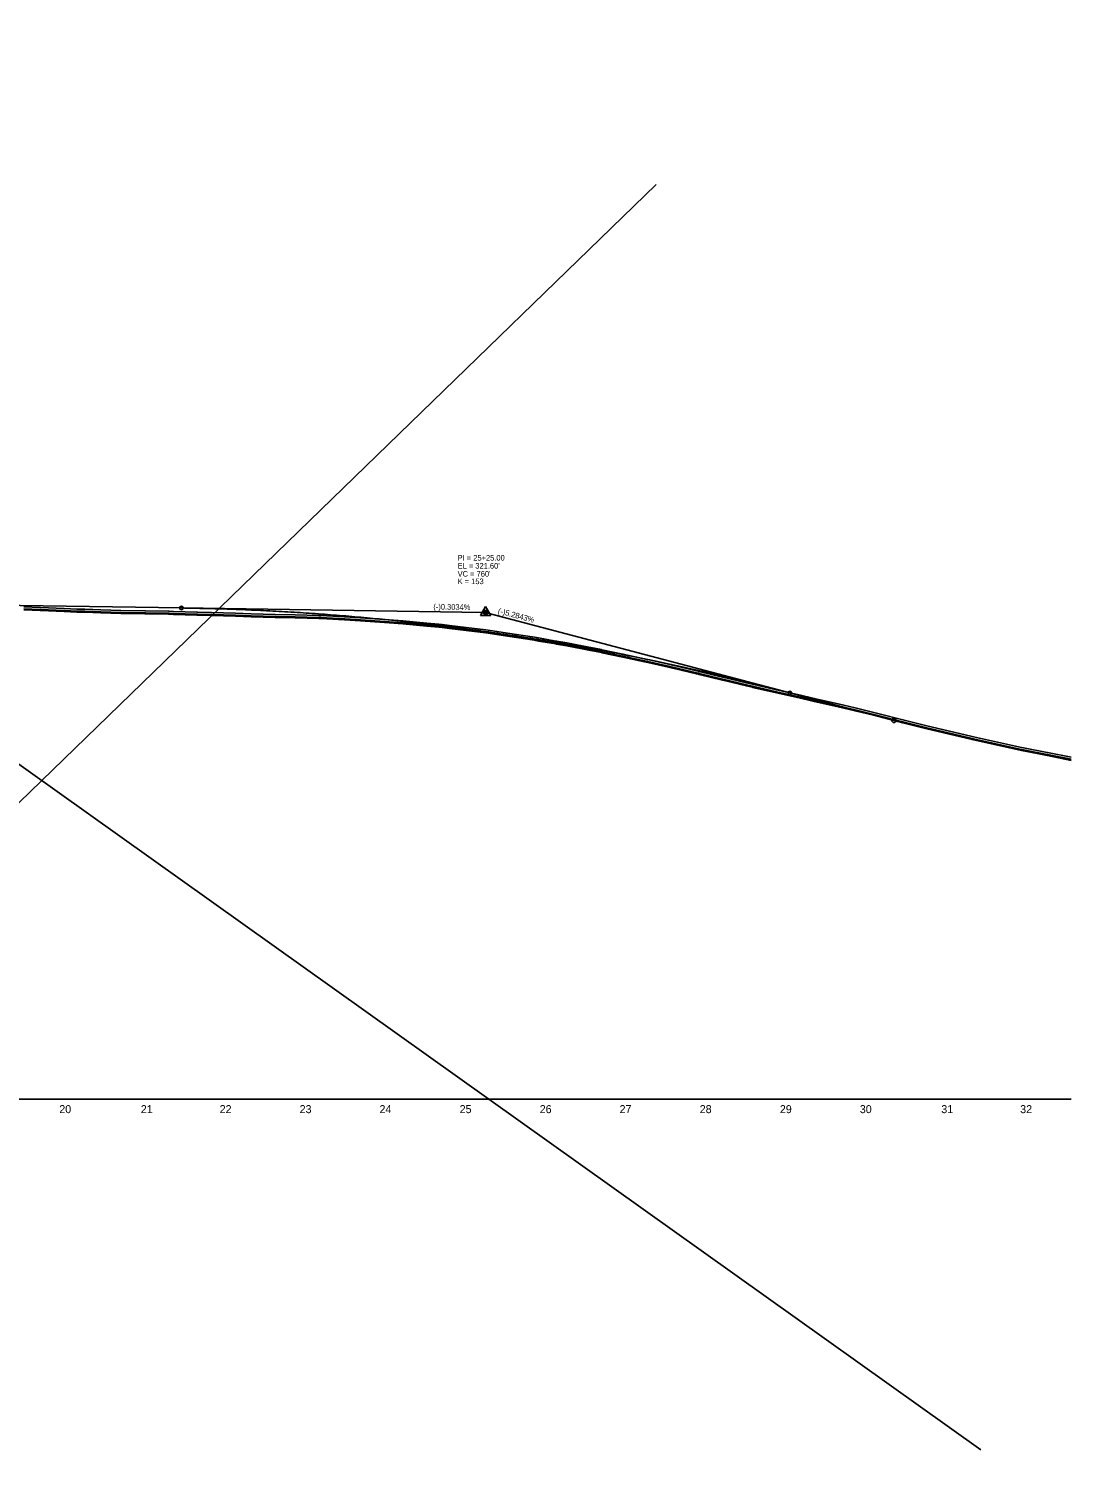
# Model space of a CAD drawing. Extents: x 2111382 to 2119088, y 667477 to 672158.
# Drawn here: x 2117786 to 2119088, y 670365 to 672158 of the extents above; entities that cross this region are included whole.
import ezdxf

# ---------------------------------------------------------------- set-up
doc = ezdxf.new("R2010")
doc.units = 0
for name, color, linetype in [('Exist Profile Cell', 7, 'Continuous'), ('Exist Vertical Profile Ground Line', 7, 'Continuous'), ('Exist Vertical Profile Horizontal Axis Label Major', 7, 'Continuous'), ('Prop PFL VPI Symbol CELL', 7, 'Continuous'), ('Prop Vertical Profile Curve Label', 7, 'Continuous'), ('Prop Vertical Profile Grade', 7, 'Continuous'), ('Prop Vertical Profile Grade Label', 7, 'Continuous'), ('Prop VPI Label', 7, 'Continuous'), ('Scratch_Level_2', 7, 'Continuous'), ('Scratch_Level_3', 7, 'Continuous')]:
    doc.layers.add(name, color=color, linetype=linetype)

msp = doc.modelspace()

# ---------------------------------------------------------------- linework, layer by layer
at = {"layer": 'Exist Profile Cell'}
msp.add_line((2116831.9, 670820.2), (2119088.5, 670820.2), dxfattribs=at)
at = {"layer": 'Exist Vertical Profile Ground Line'}
for points in [[(2117779.9, 671431.7), (2117800.2, 671431), (2117800.7, 671430.9), (2117830.4, 671429.6), (2117846, 671428.9), (2117856.2, 671428.6), (2117876, 671428), (2117876.3, 671428), (2117901.3, 671427.2), (2117931.3, 671426.7), (2117931.8, 671426.7), (2117960.5, 671426.1), (2117961.4, 671426.1), (2117966.8, 671426), (2117996.2, 671425.1), (2117996.8, 671425.1), (2118014.1, 671424.6), (2118014.5, 671424.6), (2118044.4, 671423.6), (2118063.8, 671423), (2118093.8, 671422.2), (2118119, 671421.6), (2118148.6, 671420.8), (2118149.1, 671420.8), (2118150.7, 671420.7), (2118151.2, 671420.7), (2118180.7, 671419.1), (2118181, 671419.1), (2118200.5, 671418), (2118230.6, 671415.8), (2118253.6, 671414.2), (2118283.5, 671411.4), (2118298.6, 671410), (2118302.5, 671409.7), (2118311.9, 671408.5), (2118332.5, 671406), (2118357, 671403), (2118387.2, 671398.4), (2118415.1, 671394.1), (2118415.5, 671394), (2118423, 671392.7), (2118444.6, 671389), (2118445.5, 671388.8), (2118458.5, 671386.5), (2118487.8, 671380.9), (2118488.4, 671380.8), (2118501.6, 671378.2), (2118502.2, 671378.1), (2118528.4, 671372.6), (2118555.2, 671366.7), (2118555.6, 671366.6), (2118585.3, 671360.1), (2118590.2, 671358.9), (2118590.8, 671358.7), (2118620.2, 671351.7), (2118622.8, 671351.1), (2118623.5, 671350.9), (2118652.8, 671343.8), (2118653.3, 671343.7), (2118682.7, 671336.5), (2118690, 671334.9), (2118690.3, 671334.8), (2118720.2, 671328), (2118750, 671321.1), (2118763.8, 671318), (2118767.4, 671317.2), (2118797.3, 671310.4), (2118818.4, 671305.3), (2118848.5, 671298.2)], [(2118848.5, 671298.2), (2118878.2, 671290.6), (2118908.1, 671283.1), (2118934.5, 671276.7), (2118964.5, 671269.5), (2118966.5, 671269.1), (2118996.4, 671262.5), (2119026.4, 671255.9), (2119028.6, 671255.4), (2119058.5, 671249.5), (2119058.9, 671249.5), (2119088.5, 671243.6)]]:
    msp.add_lwpolyline(points, dxfattribs=at)
at = {"layer": 'Prop PFL VPI Symbol CELL'}
for p, q in [((2118356.9, 671435.7), (2118350.4, 671424.5)), ((2118356.9, 671435.7), (2118363.4, 671424.5)), ((2118350.4, 671424.5), (2118363.4, 671424.5))]:
    msp.add_line(p, q, dxfattribs=at)
for radius in [1.75, 1.2]:
    msp.add_circle((2118356.9, 671428.2), radius, dxfattribs=at)
at = {"layer": 'Prop Vertical Profile Curve Label'}
for centre in [(2117976.9, 671434), (2118736.9, 671327.8)]:
    msp.add_circle(centre, 2.25, dxfattribs=at)
at = {"layer": 'Prop Vertical Profile Grade'}
for p, q in [((2117706.9, 671438.1), (2117976.9, 671434)), ((2118736.9, 671327.8), (2118866.9, 671293.5))]:
    msp.add_line(p, q, dxfattribs=at)
msp.add_spline([(2117976.9, 671434), (2117992.1, 671433.7), (2118007.3, 671433.4), (2118022.5, 671433), (2118037.7, 671432.5), (2118052.9, 671431.9), (2118068.1, 671431.3), (2118083.3, 671430.5), (2118098.5, 671429.7), (2118113.7, 671428.9), (2118128.9, 671427.9), (2118144.1, 671426.9), (2118159.3, 671425.8), (2118174.5, 671424.6), (2118189.7, 671423.4), (2118204.9, 671422), (2118220.1, 671420.6), (2118235.3, 671419.1), (2118250.5, 671417.6), (2118265.7, 671416), (2118280.9, 671414.2), (2118296.1, 671412.5), (2118311.3, 671410.6), (2118326.5, 671408.7), (2118341.7, 671406.7), (2118356.9, 671404.6), (2118372.1, 671402.4), (2118387.3, 671400.2), (2118402.5, 671397.9), (2118417.7, 671395.5), (2118432.9, 671393), (2118448.1, 671390.5), (2118463.3, 671387.9), (2118478.5, 671385.2), (2118493.7, 671382.4), (2118508.9, 671379.6), (2118524.1, 671376.6), (2118539.3, 671373.6), (2118554.5, 671370.6), (2118569.7, 671367.4), (2118584.9, 671364.2), (2118600.1, 671360.9), (2118615.3, 671357.5), (2118630.5, 671354.1), (2118645.7, 671350.6), (2118660.9, 671347), (2118676.1, 671343.3), (2118691.3, 671339.5), (2118706.5, 671335.7), (2118721.7, 671331.8), (2118736.9, 671327.8)], degree=3, dxfattribs=at)
at = {"layer": 'Prop VPI Label'}
for p, q in [((2117976.9, 671434), (2118354.1, 671428.3)), ((2118736.9, 671327.8), (2118359.5, 671427.5))]:
    msp.add_line(p, q, dxfattribs=at)
for centre in [(2118356.9, 671428.2), (2118866.9, 671293.5)]:
    msp.add_circle(centre, 2.75, dxfattribs=at)
at = {"layer": 'Scratch_Level_2'}
for points in [[(2117779.9, 671433), (2117800.2, 671432.2), (2117800.7, 671432.2), (2117830.4, 671430.9), (2117846, 671430.2), (2117856.2, 671429.9), (2117876, 671429.3), (2117876.3, 671429.3), (2117901.3, 671428.5), (2117931.3, 671427.9), (2117931.8, 671427.9), (2117960.5, 671427.4), (2117961.4, 671427.4), (2117966.8, 671427.2), (2117996.2, 671426.4), (2117996.8, 671426.3), (2118014.1, 671425.8), (2118014.5, 671425.8), (2118044.4, 671424.9), (2118063.8, 671424.2), (2118093.8, 671423.5), (2118119, 671422.9), (2118148.6, 671422), (2118149.1, 671422), (2118150.7, 671422), (2118151.2, 671421.9), (2118180.7, 671420.3), (2118181, 671420.3), (2118200.5, 671419.3), (2118230.6, 671417.1), (2118253.6, 671415.4), (2118283.5, 671412.7), (2118298.6, 671411.3), (2118302.5, 671410.9), (2118311.9, 671409.8), (2118332.5, 671407.3), (2118357, 671404.3), (2118387.2, 671399.6), (2118415.1, 671395.3), (2118415.5, 671395.3), (2118423, 671394), (2118444.6, 671390.2), (2118445.5, 671390.1), (2118458.5, 671387.8), (2118487.8, 671382.1), (2118488.4, 671382), (2118501.6, 671379.5), (2118502.2, 671379.3), (2118528.4, 671373.8), (2118555.2, 671367.9), (2118555.6, 671367.8), (2118585.3, 671361.3), (2118590.2, 671360.1), (2118590.8, 671360), (2118620.2, 671353), (2118622.8, 671352.4), (2118623.5, 671352.2), (2118652.8, 671345.1), (2118653.3, 671344.9), (2118682.7, 671337.8), (2118690, 671336.1), (2118690.3, 671336.1), (2118720.2, 671329.2), (2118750, 671322.4), (2118763.8, 671319.3), (2118767.4, 671318.5), (2118797.3, 671311.6), (2118818.4, 671306.6), (2118848.5, 671299.4)], [(2118848.5, 671299.4), (2118878.2, 671291.9), (2118908.1, 671284.3), (2118934.5, 671278), (2118964.5, 671270.8), (2118966.5, 671270.3), (2118996.4, 671263.7), (2119026.4, 671257.1), (2119028.6, 671256.7), (2119058.5, 671250.8), (2119058.9, 671250.7), (2119088.5, 671244.9)]]:
    msp.add_lwpolyline(points, dxfattribs=at)
at = {"layer": 'Scratch_Level_3'}
for p, q in [((2116483.7, 672157.9), (2118975.5, 670382)), ((2116922.9, 670365.1), (2118570, 671963.4))]:
    msp.add_line(p, q, dxfattribs=at)
for points in [[(2117779.9, 671435.5), (2117800.2, 671434.7), (2117800.7, 671434.7), (2117830.4, 671433.4), (2117846, 671432.7), (2117856.2, 671432.4), (2117876, 671431.8), (2117876.3, 671431.8), (2117901.3, 671431), (2117931.3, 671430.4), (2117931.8, 671430.4), (2117960.5, 671429.9), (2117961.4, 671429.9), (2117966.8, 671429.7), (2117996.2, 671428.9), (2117996.8, 671428.8), (2118014.1, 671428.3), (2118014.5, 671428.3), (2118044.4, 671427.4), (2118063.8, 671426.7), (2118093.8, 671426), (2118119, 671425.4), (2118148.6, 671424.5), (2118149.1, 671424.5), (2118150.7, 671424.5), (2118151.2, 671424.4), (2118180.7, 671422.8), (2118181, 671422.8), (2118200.5, 671421.8), (2118230.6, 671419.6), (2118253.6, 671417.9), (2118283.5, 671415.2), (2118298.6, 671413.8), (2118302.5, 671413.4), (2118311.9, 671412.3), (2118332.5, 671409.8), (2118357, 671406.8), (2118387.2, 671402.1), (2118415.1, 671397.8), (2118415.5, 671397.8), (2118423, 671396.5), (2118444.6, 671392.7), (2118445.5, 671392.6), (2118458.5, 671390.3), (2118487.8, 671384.6), (2118488.4, 671384.5), (2118501.6, 671382), (2118502.2, 671381.8), (2118528.4, 671376.3), (2118555.2, 671370.4), (2118555.6, 671370.3), (2118585.3, 671363.8), (2118590.2, 671362.6), (2118590.8, 671362.5), (2118620.2, 671355.5), (2118622.8, 671354.9), (2118623.5, 671354.7), (2118652.8, 671347.6), (2118653.3, 671347.4), (2118682.7, 671340.3), (2118690, 671338.6), (2118690.3, 671338.6), (2118720.2, 671331.7), (2118750, 671324.9), (2118763.8, 671321.8), (2118767.4, 671321), (2118797.3, 671314.1), (2118818.4, 671309.1), (2118848.5, 671301.9)], [(2118848.5, 671301.9), (2118878.2, 671294.4), (2118908.1, 671286.8), (2118934.5, 671280.5), (2118964.5, 671273.3), (2118966.5, 671272.8), (2118996.4, 671266.2), (2119026.4, 671259.6), (2119028.6, 671259.2), (2119058.5, 671253.3), (2119058.9, 671253.2), (2119088.5, 671247.4)]]:
    msp.add_lwpolyline(points, dxfattribs=at)

# ---------------------------------------------------------------- texts
at = {"layer": 'Exist Vertical Profile Horizontal Axis Label Major'}
for s, p in [('20', (2117824.3, 670802.7)), ('21', (2117926.1, 670802.7)), ('22', (2118024.6, 670802.7)), ('23', (2118124.5, 670802.7)), ('24', (2118224.3, 670802.7)), ('25', (2118324.4, 670802.7)), ('26', (2118424.4, 670802.7)), ('27', (2118524.2, 670802.7)), ('28', (2118624.3, 670802.7)), ('29', (2118724.4, 670802.7)), ('30', (2118824.3, 670802.7)), ('31', (2118926.1, 670802.7)), ('32', (2119024.6, 670802.7))]:
    msp.add_text(s, height=10, dxfattribs=at).set_placement(p)
at = {"layer": 'Prop Vertical Profile Curve Label'}
for s, p in [("VC = 760'", (2118321.9, 671473.2)), ('K = 153', (2118321.9, 671463.8))]:
    msp.add_text(s, height=7, dxfattribs=at).set_placement(p)
at = {"layer": 'Prop Vertical Profile Grade Label'}
for s, rotation, p in [('(-)0.3034%', 359.1308, (2118291.5, 671432.2)), ('(-)5.2843%', 345.1998, (2118371.7, 671427.4))]:
    msp.add_text(s, height=7, rotation=rotation, dxfattribs=at).set_placement(p)
at = {"layer": 'Prop VPI Label'}
for s, p in [('PI = 25+25.00', (2118321.9, 671493.2)), ("EL = 321.60'", (2118321.9, 671483.2))]:
    msp.add_text(s, height=7, dxfattribs=at).set_placement(p)

doc.saveas('drawing.dxf')
